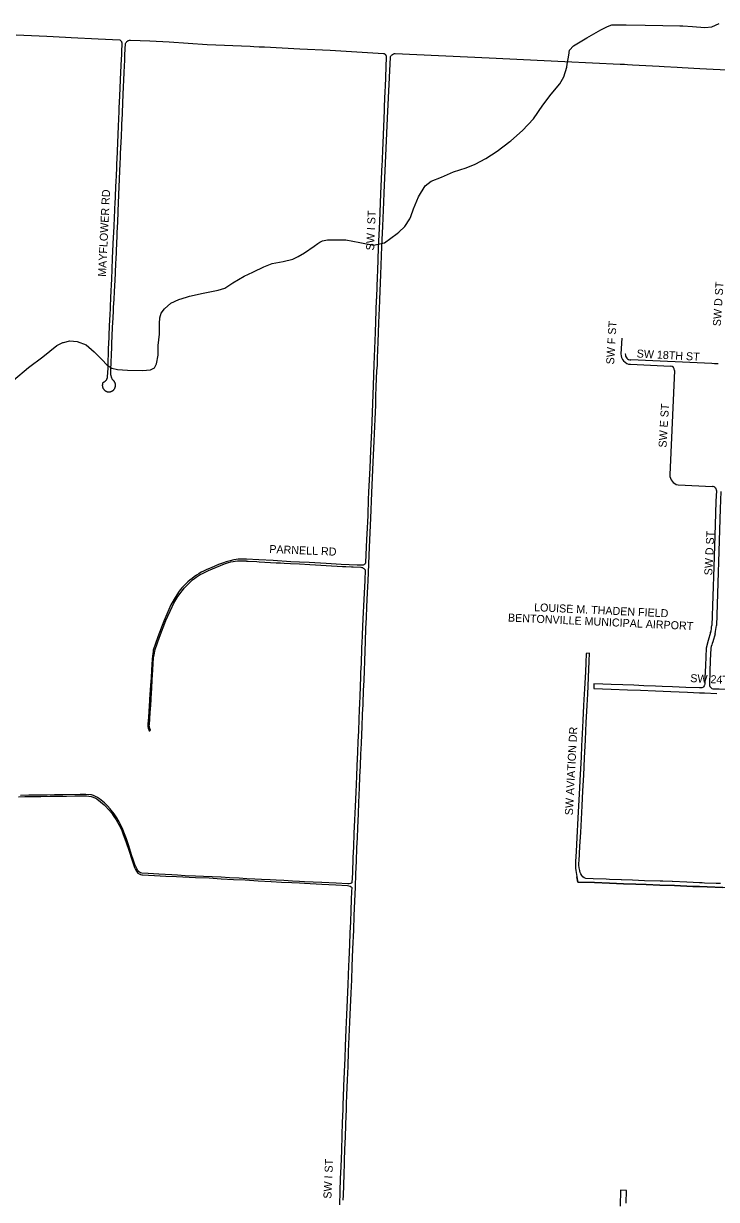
# Model space of a CAD drawing. Extents: x 0 to 712119, y 0 to 761125.
# Drawn here: x 655776 to 660107, y 736879 to 744227 of the extents above; entities that cross this region are included whole.
import ezdxf

# ---------------------------------------------------------------- set-up
doc = ezdxf.new("R2010")
doc.units = 0
for name, color, linetype in [('PAVED ROADS', 7, 'Continuous'), ('stream or creek', 7, 'Continuous'), ('street names', 7, 'Continuous')]:
    doc.layers.add(name, color=color, linetype=linetype)

msp = doc.modelspace()

# ---------------------------------------------------------------- linework, layer by layer
at = {"layer": 'PAVED ROADS'}
for points in [[(655729.9, 744157.5), (655921.2, 744147.8), (656037, 744141.6), (656072.7, 744139.7), (656073.5, 744139.6), (656241.4, 744132.6), (656377.3, 744124.7), (656380, 744123.3), (656382.5, 744121.6), (656384.7, 744119.4), (656386.5, 744117), (656387.9, 744114.4), (656389, 744111.5), (656389.5, 744108.5), (656389.7, 744105.5), (656387.8, 744048.4), (656387.1, 744031.4), (656385.8, 744003.7), (656382.1, 743924), (656375.1, 743776), (656371.8, 743699.4), (656370.8, 743678.5), (656366.9, 743586.5), (656358.1, 743377.5), (656357.3, 743355.4), (656356.4, 743334.1), (656353.7, 743268.6), (656352.9, 743247.7), (656349.1, 743152.4), (656348.1, 743132.6), (656347.2, 743113.4), (656340, 742962.4), (656338, 742919.8), (656336.7, 742892.9), (656330.5, 742761.9), (656330.2, 742755.7), (656327.9, 742697.1), (656324.9, 742624.7), (656323.9, 742599.2), (656322.1, 742553.5), (656320, 742517.6), (656319.3, 742503.4), (656318.6, 742490.9), (656318.1, 742481.7), (656317.1, 742463.5), (656316.2, 742445.8), (656314.4, 742409.8), (656312.7, 742373.9), (656311, 742338), (656309.9, 742312.3), (656309.5, 742302), (656309, 742290.7), (656308, 742266.1), (656306.6, 742230.1), (656305.3, 742194.2), (656304.1, 742158.2), (656302.9, 742122.3), (656301.8, 742074.2), (656298.9, 742019.1), (656298.7, 742017.2), (656298.5, 742015.4), (656298.1, 742013.6), (656297.7, 742011.8), (656297.2, 742010), (656296.6, 742008.3), (656295.9, 742006.5), (656295.2, 742004.8), (656294.4, 742003.2), (656293.5, 742001.6), (656292.5, 742000), (656291.5, 741998.4), (656290.4, 741996.9), (656289.3, 741995.5), (656288.1, 741994.1), (656286.8, 741992.7), (656285.5, 741991.4), (656284.1, 741990.2), (656282.7, 741989.1), (656281.2, 741987.9), (656279.7, 741986.9), (656278.1, 741985.9), (656276.5, 741985), (656274.9, 741984.2), (656273.2, 741983.4), (656271.5, 741982.7), (656271.4, 741982.7), (656271.4, 741982.7), (656270.7, 741981), (656270.1, 741979.3), (656269.6, 741977.6), (656269.2, 741975.8), (656268.8, 741974), (656268.6, 741972.2), (656268.3, 741970.4), (656268.2, 741968.6), (656268.2, 741966.8), (656268.2, 741965), (656268.3, 741963.2), (656268.5, 741961.4), (656268.8, 741959.6), (656269.2, 741957.8), (656269.5, 741956.3), (656269.6, 741956), (656270.1, 741954.3), (656270.7, 741952.6), (656271.4, 741950.9), (656271.8, 741949.8), (656272.1, 741949.2), (656272.9, 741947.6), (656273.8, 741946), (656274.7, 741944.5), (656275.7, 741943), (656276.8, 741941.5), (656278, 741940.1), (656279.2, 741938.7), (656280.4, 741937.4), (656281.8, 741936.2), (656282.1, 741935.9), (656283.1, 741935), (656284.5, 741933.9), (656286, 741932.8), (656287.5, 741931.8), (656289.1, 741930.9), (656289.9, 741930.5), (656290.7, 741930), (656292.3, 741929.3), (656294, 741928.5), (656295.7, 741927.9), (656297.4, 741927.3), (656299.2, 741926.8), (656300.9, 741926.4), (656302.7, 741926.1), (656304.1, 741925.9), (656304.5, 741925.8), (656306.3, 741925.7), (656308.1, 741925.6), (656309.9, 741925.6), (656311.8, 741925.6), (656313.6, 741925.8), (656314.5, 741925.9), (656315.4, 741926), (656317.2, 741926.3), (656318.9, 741926.7), (656320.7, 741927.2), (656322.4, 741927.7), (656324.1, 741928.3), (656325.8, 741929), (656327.5, 741929.8), (656328.6, 741930.3), (656329.1, 741930.6), (656330.6, 741931.5), (656332.2, 741932.5), (656333.7, 741933.5), (656335.1, 741934.6), (656336.5, 741935.8), (656337.8, 741937), (656339.1, 741938.3), (656340.4, 741939.6), (656341.5, 741941), (656342.6, 741942.4), (656343.7, 741943.9), (656344.6, 741945.5), (656345.5, 741947), (656346.4, 741948.7), (656347.1, 741950.3), (656347.8, 741952), (656348.4, 741953.7), (656349, 741955.4), (656349.4, 741957.2), (656349.8, 741959), (656349.8, 741959), (656349.8, 741959.1), (656350.1, 741960.7), (656350.3, 741962.5), (656350.5, 741964.4), (656350.5, 741966.2), (656350.5, 741968), (656350.4, 741969.8), (656350.3, 741971.6), (656350, 741973.4), (656350, 741973.7), (656349.9, 741973.9), (656349.7, 741975.2), (656349.3, 741977), (656348.8, 741978.7), (656348.2, 741980.4), (656347.6, 741982.1), (656346.9, 741983.8), (656346.1, 741985.4), (656345.2, 741987), (656344.3, 741988.6), (656343.3, 741990.1), (656342.2, 741991.6), (656341.1, 741993), (656339.9, 741994.4), (656338.7, 741995.7), (656337.4, 741997), (656336, 741998.2), (656334.6, 741999.3), (656333.1, 742000.4), (656332.9, 742000.5), (656331.6, 742002.9), (656330.4, 742005.3), (656329.2, 742007.7), (656328.1, 742010.2), (656327.1, 742012.7), (656326.1, 742015.2), (656325.3, 742017.8), (656324.5, 742020.3), (656323.8, 742022.9), (656323.1, 742025.6), (656322.5, 742028.2), (656322.1, 742030.8), (656321.7, 742033.5), (656321.3, 742036.2), (656321.1, 742038.9), (656320.9, 742041.6), (656320.8, 742044.3), (656320.8, 742047), (656320.9, 742049.6), (656321.1, 742052.3), (656321.3, 742055), (656321.6, 742057.7), (656322, 742060.4), (656321.8, 742062.8), (656326.7, 742205.1), (656327, 742213), (656327.7, 742228.2), (656331.8, 742326.5), (656332.1, 742331.3), (656333.4, 742355.7), (656337.1, 742427.6), (656337.7, 742439.9), (656338.7, 742455.6), (656341.7, 742503.4), (656344.7, 742553.2), (656348.2, 742623.7), (656350.2, 742666.7), (656351.2, 742686.6), (656352.5, 742712.8), (656355.3, 742770.7), (656355.8, 742781.2), (656356.9, 742808.4), (656360.7, 742899.5), (656361.7, 742922.1), (656364.4, 742986.7), (656369.5, 743112.9), (656371, 743148.9), (656371.4, 743158.7), (656379.6, 743352), (656381.5, 743390.2), (656382.6, 743414.5), (656387.8, 743522.4), (656390.5, 743582.9), (656391.1, 743596.7), (656392.6, 743630.8), (656393.8, 743658), (656394.4, 743671), (656399.3, 743785.9), (656405.4, 743918.5), (656407.3, 743965.4), (656408.3, 743993.3), (656409.8, 744032.3), (656413.2, 744103.5), (656415.6, 744107.7), (656418.5, 744111.5), (656421.9, 744114.9), (656425.7, 744117.8), (656429.8, 744120.3), (656434.2, 744122.2), (656438.8, 744123.6), (656443.5, 744124.3), (656564.7, 744118.6), (656685.8, 744112.8), (656923.5, 744097.1), (657192.5, 744085.2), (657215.8, 744084.1), (657248, 744082.7), (657272.7, 744081.6), (657281.7, 744081.2), (657502.2, 744069.8), (657691.7, 744060.1), (658026.7, 744040.3), (658028.9, 744039.5), (658031, 744038.6), (658032.9, 744037.4), (658034.8, 744036), (658035.9, 744035), (658037.5, 744033.4), (658038.9, 744031.6), (658040.2, 744029.6), (658041.2, 744027.6), (658042, 744025.5), (658042.7, 744023.3), (658043.1, 744021), (658043.2, 744018.8), (658043.2, 744017.5), (658035.6, 743831.1), (658034.6, 743807.8), (658034.5, 743805.2), (658030.7, 743708.9), (658030.6, 743708.1), (658029.7, 743686.4), (658021.4, 743480.3), (658021, 743470.2), (658019.9, 743445.6), (658016.6, 743367.1), (658015.7, 743346.5), (658007.9, 743165.2), (658000.4, 742988.6), (657993.3, 742826.4), (657988.8, 742681.4), (657987.1, 742643.9), (657981.5, 742517.9), (657981.1, 742508.2), (657980.8, 742502.9), (657972.7, 742295.9), (657965.1, 742097.2), (657960.2, 741965.9), (657956.2, 741852.9), (657952.8, 741739.6), (657950.5, 741684.4), (657944.8, 741556.7), (657939.8, 741451.7), (657932.4, 741299.8), (657932.2, 741295.1), (657930.8, 741256.9), (657927, 741153.8), (657920.8, 741035.8), (657919.1, 741004.1), (657919.1, 741003.1), (657913.8, 740858.8), (657912.4, 740855.4), (657910.5, 740852.3), (657908.1, 740849.5), (657905.4, 740847.1), (657902.4, 740845.1), (657899, 740843.6), (657895.5, 740842.7), (657891.9, 740842.3), (657860.6, 740842.4), (657760.1, 740847.5), (657666.4, 740852.5), (657560.8, 740859), (657501.3, 740861.7), (657446.3, 740864.2), (657335.3, 740870.9), (657246.8, 740875.1), (657170.3, 740880.3), (657170.3, 740880.3), (657157, 740880.8), (657143.8, 740880.9), (657130.5, 740880.5), (657117.3, 740879.6), (657104.1, 740878.4), (657090.9, 740876.7), (657066.6, 740870), (657042.4, 740862.7), (657018.4, 740854.7), (656994.7, 740846), (656971.2, 740836.8), (656947.9, 740826.9), (656932.1, 740820.5), (656916.5, 740813.5), (656901.1, 740806), (656886.1, 740797.9), (656871.3, 740789.3), (656856.9, 740780.1), (656842.8, 740770.5), (656829.1, 740760.3), (656815.7, 740749.7), (656802.7, 740738.6), (656783.7, 740719.9), (656765.9, 740700), (656749.2, 740679.2), (656733.9, 740657.4), (656723.2, 740640.3), (656696.7, 740594.4), (656652, 740492), (656614.6, 740394.8), (656586.4, 740311.5), (656583, 740282.3), (656582.3, 740278.4), (656578.8, 740251.3), (656576.8, 740224), (656574.9, 740185.6), (656572.6, 740139.3), (656569.4, 740092.8), (656565, 740034.8), (656563.5, 740003.3), (656563.2, 739996.5), (656558.9, 739930.9), (656556.1, 739891), (656553.2, 739851.7), (656552.1, 739842.2), (656552.6, 739832.6), (656554.7, 739823.2), (656558.4, 739814.3), (656559, 739813), (656562, 739808.1), (656562.4, 739807.4), (656562.6, 739807.5), (656568.9, 739811.9), (656565, 739821.6), (656562.8, 739831.8), (656562, 739842.3), (656562.2, 739846.1), (656564.3, 739882.9), (656568.1, 739921.1), (656570.9, 739966.9), (656573.4, 740003.3), (656574, 740012.2), (656577.2, 740074), (656580, 740126.1), (656583.3, 740188.2), (656585.1, 740225.6), (656588.5, 740262.8), (656589.5, 740271.3), (656598.6, 740315.8), (656626.5, 740392.6), (656664.2, 740496.9), (656705.5, 740581.8), (656715.5, 740604.1), (656727, 740625.6), (656739.8, 740646.4), (656754, 740666.3), (656767.1, 740682.5), (656781.9, 740700.8), (656797.8, 740718.2), (656810.2, 740730.2), (656820.9, 740740.5), (656832, 740750.2), (656843.6, 740759.4), (656855.6, 740768.1), (656868, 740776.2), (656880.7, 740783.7), (656893.7, 740790.7), (656907.1, 740797), (656931.6, 740808.7), (656956.4, 740820), (656981.4, 740830.7), (657006.6, 740841), (657032, 740850.7), (657057.6, 740860), (657071.3, 740862.8), (657085.1, 740865.2), (657099, 740867.2), (657112.9, 740868.7), (657126.9, 740869.7), (657140.9, 740870.2), (657154.9, 740870.3), (657169.4, 740870), (657169.4, 740870), (657169.3, 740868.5), (657180, 740867.9), (657233.8, 740864.8), (657249.1, 740863.9), (657355.8, 740858.1), (657382.5, 740856.6), (657404.6, 740855.4), (657444.8, 740853.2), (657501.3, 740850.2), (657565.3, 740846.9), (657566, 740846.8), (657601.4, 740844.5), (657668.4, 740840.2), (657769.9, 740835.3), (657789.7, 740834.2), (657826.6, 740832.3), (657836.1, 740831.8), (657884.7, 740829.9), (657889.8, 740828.8), (657894.7, 740827.1), (657899.3, 740824.7), (657903.5, 740821.8), (657907.4, 740818.4), (657910.7, 740814.4), (657908.7, 740745.8), (657902.2, 740627.7), (657896.2, 740507.6), (657891.7, 740409.6), (657889.9, 740352), (657889.1, 740336.3), (657888.9, 740322), (657885.2, 740228.6), (657883, 740172.5), (657883, 740172.3), (657882.2, 740144.7), (657880.4, 740084.5), (657878, 740024.8), (657876.2, 739977.2), (657874.5, 739938.1), (657872.5, 739880.9), (657868.9, 739806.2), (657866.2, 739741.2), (657863.3, 739673), (657859.6, 739589.3), (657857.6, 739523.8), (657852.8, 739424.5), (657848.4, 739334.6), (657844.8, 739251.1), (657841.1, 739166.6), (657838.4, 739083.4), (657834.8, 739013), (657831.3, 738920.3), (657828.7, 738857.1), (657821.9, 738853.7), (657811.9, 738851), (657801.9, 738850.2), (657729, 738854.5), (657640.8, 738859.1), (657531.7, 738864.1), (657501.1, 738866.1), (657456.5, 738868.4), (657403.5, 738871.7), (657354.2, 738873.8), (657317.3, 738875.6), (657263.8, 738878.5), (657220.8, 738880.7), (657171.2, 738883.3), (657123.2, 738886.3), (657063, 738888.9), (657010.6, 738892.5), (656955, 738894.2), (656900.4, 738897.3), (656851.4, 738899.9), (656786.3, 738902.2), (656738, 738905.6), (656703.2, 738907.1), (656620.5, 738911.1), (656554, 738914.9), (656514.5, 738918), (656507, 738920.3), (656500.1, 738924.1), (656494.1, 738929.2), (656489.3, 738935.5), (656485.8, 738942.5), (656485.4, 738943.6), (656472.3, 738972.8), (656460.7, 739002.7), (656450.6, 739033.1), (656446.7, 739046.2), (656433.7, 739089.7), (656419.1, 739132.6), (656411.3, 739154), (656396.6, 739189.9), (656380.5, 739225.2), (656373.9, 739238.7), (656358.6, 739263.6), (656342, 739287.7), (656324.2, 739310.8), (656317.3, 739318.9), (656299.7, 739338.4), (656281, 739356.7), (656261.2, 739373.8), (656249.8, 739382.8), (656238.4, 739390.9), (656226.2, 739397.7), (656213.3, 739403), (656199.9, 739406.8), (656196.7, 739407.4), (656165.7, 739409.4), (656134.7, 739409.8), (656130.3, 739409.7), (656022.2, 739407.3), (655968.8, 739407), (655922.5, 739406.3), (655868.2, 739406.3), (655809.5, 739405), (655757.7, 739403.9)], [(657773.5, 736873.8), (657774.7, 736905.1), (657776.9, 736966.2), (657777, 736968), (657780, 737037.5), (657780.1, 737039.4), (657782, 737100.9), (657782.7, 737121.4), (657784.9, 737191.6), (657787.6, 737270.1), (657787.7, 737272.9), (657789.4, 737340.2), (657789.6, 737349.4), (657794.3, 737443.3), (657795.5, 737477.2), (657797.5, 737531.2), (657799.8, 737626.6), (657804.2, 737709), (657807.6, 737802.9), (657811.8, 737895.8), (657815.2, 737986.8), (657819.8, 738080.4), (657823.3, 738168.6), (657827.1, 738251.6), (657829.8, 738334.2), (657834.1, 738444), (657839.4, 738560.9), (657843.1, 738652.9), (657846.8, 738743.1), (657849.9, 738831.2), (657853.2, 738913.5), (657856.5, 738992), (657859.9, 739075.6), (657862.6, 739139.1), (657865, 739201.9), (657868.6, 739289.5), (657871.3, 739360.5), (657875.3, 739450.8), (657878.5, 739518.9), (657881.7, 739587.9), (657884.5, 739660.9), (657887.4, 739729.2), (657890.1, 739785.1), (657892.4, 739832.3), (657895.1, 739910.5), (657897.9, 739972.1), (657898.2, 739977.2), (657901.6, 740059.4), (657903.9, 740122.7), (657906.2, 740183.3), (657908.7, 740244.9), (657910.6, 740304.2), (657912.4, 740365.8), (657915.7, 740446.3), (657919.1, 740514.8), (657922, 740582.6), (657926.5, 740669.6), (657930.7, 740745.4), (657939, 740955.7), (657946.5, 741135.9), (657953.5, 741295.6), (657962.1, 741485.6), (657968, 741618.2), (657973.2, 741754.6), (657976.9, 741843.2), (657978.3, 741896.2), (657980.1, 741958.9), (657985.1, 742056.6), (657987.3, 742092.9), (657988.9, 742136.9), (657991.5, 742236.9), (657996.3, 742357.6), (658002.2, 742494.4), (658002.5, 742502.9), (658008.1, 742658.6), (658015.5, 742834.1), (658021.5, 742960.7), (658027.7, 743110.9), (658030.1, 743168.7), (658037.8, 743355.1), (658050.6, 743635.3), (658069.4, 744018.2), (658070.5, 744020.7), (658072.2, 744023.7), (658074.2, 744026.6), (658076.5, 744029.2), (658079, 744031.7), (658081.8, 744033.8), (658083.2, 744034.8), (658086.2, 744036.5), (658089.4, 744038), (658092.7, 744039.1), (658096.1, 744039.9), (658099.6, 744040.4), (658099.6, 744040.4), (658686.1, 744013.8), (659159.6, 743991.1), (659505, 743974.3), (659526.3, 743973.3), (659532.4, 743973), (659551.4, 743971.9), (659582.9, 743970.1), (659748.5, 743960.6), (659779.5, 743958.8), (659860.7, 743954.2), (659892.3, 743952.4), (660002.1, 743946.6), (660213.8, 743935.4)], [(659514.8, 742261.5), (659510.3, 742164.2)], [(659537.3, 742163), (659537.5, 742163)], [(659570.6, 742097.9), (659819.7, 742086.2)], [(660117.9, 742100.6), (660095.5, 742101.2), (660077.3, 742101.9), (659571.9, 742124.8)], [(659845, 742058.5), (659815, 741407.6)], [(659867.1, 741344.5), (660082.1, 741334.2)], [(660106.9, 741308.9), (660103.6, 741241), (660098.3, 741094), (660089.6, 740831.7), (660077.6, 740466.4)], [(660135.3, 741303.8), (660130.6, 741194.3), (660106.6, 740466.4)], [(660070.5, 740422.4), (660055.8, 740370.9), (660042.8, 740324.6), (660038.5, 740216.6), (660035.4, 740138.5), (660034.2, 740100.1), (660033, 740093.7), (660030.3, 740087.8), (660026.3, 740082.8), (660021.1, 740078.8), (660015.1, 740076.3), (660008.7, 740075.3), (660005.7, 740075.4), (660001, 740075.5), (659916.6, 740078.5), (659832.9, 740082.1), (659768.2, 740085), (659726.3, 740085.8), (659652.6, 740089.4), (659591.4, 740091.8), (659521.4, 740094.8), (659448.7, 740097.6), (659397.5, 740099.6), (659340.6, 740101.4), (659340.3, 740072.5), (659394.8, 740070.1), (659449.6, 740068.4), (659550.6, 740064), (659632.1, 740060.5), (659725, 740057.5), (659821.8, 740053.5), (659926.5, 740049.2), (660001, 740045.8), (660032.2, 740044.4), (660108.9, 740041.5)], [(660098.4, 740414.5), (660083.7, 740363)], [(660071.6, 740324.6), (660068.5, 740246.6), (660065.8, 740178.7), (660063.3, 740099.8), (660063, 740097.4), (660063.4, 740091.1), (660065.4, 740085), (660068.8, 740079.7), (660073.5, 740075.4), (660079.1, 740072.3), (660085.2, 740070.8), (660124.2, 740070.2), (660197, 740067.4), (660254.1, 740064.6), (660318.8, 740062), (660381.5, 740059.5), (660475.9, 740055), (660503, 740054.9), (660563, 740052.5), (660575.9, 740052), (660642.7, 740049.3), (660740.5, 740045.4)], [(660131.9, 738852.8), (660105.2, 738853.6), (660031.8, 738856), (660016.9, 738856.5), (660000.7, 738857.2), (659921.8, 738860.7), (659832.1, 738865.2), (659830, 738865.3), (659772.3, 738867.1), (659754.4, 738867.6), (659657.4, 738870.8), (659581.6, 738873.7), (659512.9, 738876.3), (659511, 738876.3), (659438.8, 738878.8), (659418.4, 738879.6), (659337, 738882.2), (659290.2, 738884), (659281.1, 738889.4), (659272.8, 738896), (659265.7, 738903.8), (659259.8, 738912.7), (659255.3, 738922.2), (659252.3, 738932.4), (659252, 738933.9), (659248.9, 738950.6), (659247.4, 738967.5), (659247.4, 738984.4), (659248.1, 738993.9), (659253.4, 739085.9), (659258.5, 739172.7), (659263.6, 739255.4), (659267.9, 739338.9), (659272.6, 739433.1), (659277.4, 739530.7), (659282.8, 739636), (659288.4, 739751.9), (659293.6, 739859.6), (659298.8, 739965), (659300.5, 740002.5), (659302, 740035.9), (659307.5, 740140.2), (659312.2, 740242), (659313.4, 740291.9), (659293.7, 740291.4), (659293.6, 740291.4), (659293.6, 740291.3), (659290.4, 740232.2), (659287.4, 740175.3), (659281.9, 740070.7), (659278.5, 740002.5), (659276.8, 739966), (659272, 739872.5), (659268.1, 739789.6), (659264.3, 739713.6), (659260.7, 739642.9), (659256.5, 739569), (659254.8, 739534.4), (659252.9, 739499.1), (659252.6, 739491.8), (659248.4, 739410.6), (659244.9, 739337.7), (659240.8, 739262.1), (659234.8, 739140.1), (659229.2, 739052.6), (659225.7, 738990.6), (659225.2, 738970.9), (659226.2, 738951.2), (659228.8, 738931.7), (659230.5, 738923.3), (659232.8, 738908.4), (659233.5, 738898.2), (659234.1, 738894.7), (659240.1, 738862), (659344.9, 738858.8), (659437.9, 738855.3), (659526.9, 738851.1), (659603.7, 738849.4), (659667.6, 738847.4), (659754.1, 738843.9), (659844.8, 738840.6), (659958.5, 738835.3), (660000.7, 738834), (660048.7, 738832.6), (660146.3, 738827.8)], [(655743.8, 739395.3), (655784.2, 739396.3), (655830.4, 739397), (655884.6, 739397.2), (655943.1, 739398.4), (655997.2, 739399.7), (656045.1, 739399.4), (656096.8, 739400.6), (656150.4, 739400.7), (656169.4, 739401), (656183.8, 739400), (656198, 739397.3), (656211.9, 739393.1), (656225.2, 739387.4), (656234.5, 739382.4), (656257.6, 739363.8), (656279.7, 739344.1), (656288.3, 739335.9), (656307.1, 739315.9), (656324.7, 739294.9), (656341.1, 739272.9), (656355.6, 739250.8), (656373.1, 739217.7), (656389.1, 739183.8), (656397.3, 739164.8), (656417.8, 739109.1), (656435.4, 739054.5), (656451.9, 739004.1), (656470, 738954.2), (656470.2, 738953.6), (656475.1, 738941.5), (656481.5, 738930.1), (656485, 738924.9), (656491.1, 738918.6), (656498.3, 738913.5), (656506.3, 738909.7), (656514.8, 738907.5), (656519.3, 738906.9), (656595.2, 738903.5), (656665, 738899.8), (656731.4, 738896.5), (656849.9, 738891.8), (656936.3, 738887.9), (657010.9, 738883.4), (657088.2, 738879.3), (657161.2, 738876), (657242.9, 738870.6), (657323.1, 738866.6), (657389, 738862.5), (657453, 738858.9), (657500.7, 738856.9), (657531.3, 738855.5), (657640.2, 738849.1), (657728.4, 738844.3), (657800.8, 738841), (657809.2, 738839.3), (657817.2, 738836.2), (657824.5, 738831.7), (657827.6, 738829), (657827.6, 738828.2), (657826.6, 738803.3), (657824.5, 738752.5), (657822.1, 738683.6), (657819.1, 738613.3), (657816.2, 738544.1), (657812.7, 738471.5), (657808.2, 738376.6), (657806.8, 738339), (657802.8, 738222.8), (657798.6, 738126.1), (657794.2, 738033), (657790.2, 737940.1), (657786.4, 737837.4), (657783.1, 737761.2), (657779.8, 737675.8), (657775.5, 737589.9), (657772.9, 737517), (657771.8, 737477.2), (657770.7, 737440.6), (657767.7, 737360.6), (657764.4, 737281.2), (657762.4, 737184.8), (657758.6, 737081.8), (657755.7, 737009.9), (657753.4, 736928.9), (657749.7, 736845.1)], [(660581.2, 738812.2), (660508.7, 738814.5), (660417.6, 738818.4), (660325.1, 738822), (660234.8, 738824.7), (660146.3, 738827.8), (660048.7, 738832.6), (660000.7, 738834), (659958.5, 738835.3), (659844.8, 738840.6), (659754.1, 738843.9), (659667.6, 738847.4), (659603.7, 738849.4), (659526.9, 738851.1), (659437.9, 738855.3), (659344.9, 738858.8), (659240.1, 738862), (659234.1, 738894.7)], [(659541.9, 736854.7), (659544.1, 736933.9), (659508, 736936.4), (659505.7, 736837.8)]]:
    msp.add_lwpolyline(points, dxfattribs=at)
for centre, radius, start, end in [((659573.6, 742161.2), 63.4, 177.27095, 267.27095), ((659573.6, 742161.2), 36.4, 177.12458, 267.34375), ((659818.5, 742059.7), 26.5, 357.41804, 87.41804), ((659878.7, 741407.2), 63.7, 179.63737, 259.57299), ((660081.9, 741309.2), 25, 359.2043, 89.46695), ((659892.2, 740473.4), 185.5, 344.04497, 357.83724), ((659892.2, 740473.4), 214.5, 344.04497, 358.11085), ((660459, 740223.7), 400.3, 159.63696, 165.39754)]:
    msp.add_arc(centre, radius, start, end, dxfattribs=at)
at = {"layer": 'stream or creek'}
msp.add_lwpolyline([(655712.7, 741997.7), (655806.5, 742077.4), (655897.1, 742144.5), (655984.6, 742214.8), (656022.2, 742233.5), (656025.8, 742234.4), (656064.2, 742244.5), (656110.2, 742240.5), (656166.2, 742220.5), (656218.2, 742175.5), (656268.2, 742126.5), (656296.2, 742095.5), (656328.2, 742073.5), (656362.2, 742065.5), (656425.2, 742061.5), (656519.2, 742058.5), (656570.2, 742063.5), (656594.2, 742075.5), (656607.2, 742101.5), (656616.2, 742154.5), (656618.2, 742214.5), (656625.2, 742286.5), (656625.2, 742352.5), (656627.2, 742388.4), (656636.2, 742417.5), (656656.4, 742443.5), (656696.2, 742478.9), (656746, 742503.2), (656794.4, 742517.5), (656813.5, 742523.1), (656898.7, 742541.9), (656991.5, 742561.8), (657033.5, 742574), (657084.4, 742606.1), (657154.1, 742648.1), (657209.1, 742674.1), (657212.7, 742675.7), (657276.9, 742707.8), (657328.9, 742727.7), (657398.5, 742741), (657459.4, 742754.3), (657492.5, 742770.9), (657531.3, 742795.2), (657592.1, 742836.1), (657614.9, 742852.5), (657627.5, 742861.5), (657645.2, 742870.4), (657675.1, 742875.9), (657730.3, 742875.9), (657790.1, 742875.9), (657877.4, 742858.2), (657963.7, 742841.6), (658031.2, 742856), (658111.9, 742915.7), (658120.6, 742924), (658158.4, 742960), (658190.4, 743006.5), (658196.3, 743022.1), (658213.7, 743068.4), (658244.6, 743144.7), (658286.6, 743213.3), (658323.2, 743243.1), (658387.3, 743267.5), (658462.5, 743300.6), (658542.1, 743326), (658599.7, 743348.2), (658666, 743383.6), (658736.8, 743428.9), (658816.4, 743489.8), (658822, 743494.6), (658894.9, 743558.3), (658962.4, 743631.3), (659021, 743717.6), (659074.1, 743785), (659127.2, 743851.4), (659153.8, 743894.5), (659171.4, 743954.3), (659174.6, 743974), (659183.6, 744030.6), (659188, 744060.4), (659213.5, 744087), (659297.5, 744137.9), (659383.8, 744188.7), (659425.8, 744209.8), (659452.4, 744219.7), (659543, 744218.6), (659661.4, 744216.4), (659770.9, 744215.3), (659878.2, 744213.1), (659896.4, 744212.3), (659957.8, 744209.7), (660035.2, 744203.1), (660078.4, 744207.5), (660123.7, 744227.4)], dxfattribs=at)

# ---------------------------------------------------------------- texts
at = {"layer": 'street names'}
for s, rotation, p in [('MAYFLOWER RD', 87.2484, (656290.6, 742643.9)), ('SW I ST', 87.46873, (657966.6, 742808.8)), ('SW D ST', 86.34173, (660133.9, 742334.7)), ('SW F ST', 86.48288, (659466.8, 742096)), ('SW 18TH ST', 356.93067, (659607.5, 742140.8)), ('SW E ST', 86.48288, (659794.4, 741576.2)), ('SW D ST', 86.98382, (660080.3, 740777.7)), ('PARNELL RD', 357.62533, (657311.2, 740919)), ('BENTONVILLE MUNICIPAL AIRPORT', 357.33984, (658803, 740490.8)), ('LOUISE M. THADEN FIELD', 357.33984, (658966.5, 740555.4)), ('SW 24TH ST', 357.03814, (659942.4, 740112.2)), ('SW AVIATION DR', 87.0215, (659209.2, 739278.7)), ('SW I ST', 87.46873, (657699.7, 736882.6))]:
    msp.add_text(s, height=50, rotation=rotation, dxfattribs=at).set_placement(p)

doc.saveas('drawing.dxf')
